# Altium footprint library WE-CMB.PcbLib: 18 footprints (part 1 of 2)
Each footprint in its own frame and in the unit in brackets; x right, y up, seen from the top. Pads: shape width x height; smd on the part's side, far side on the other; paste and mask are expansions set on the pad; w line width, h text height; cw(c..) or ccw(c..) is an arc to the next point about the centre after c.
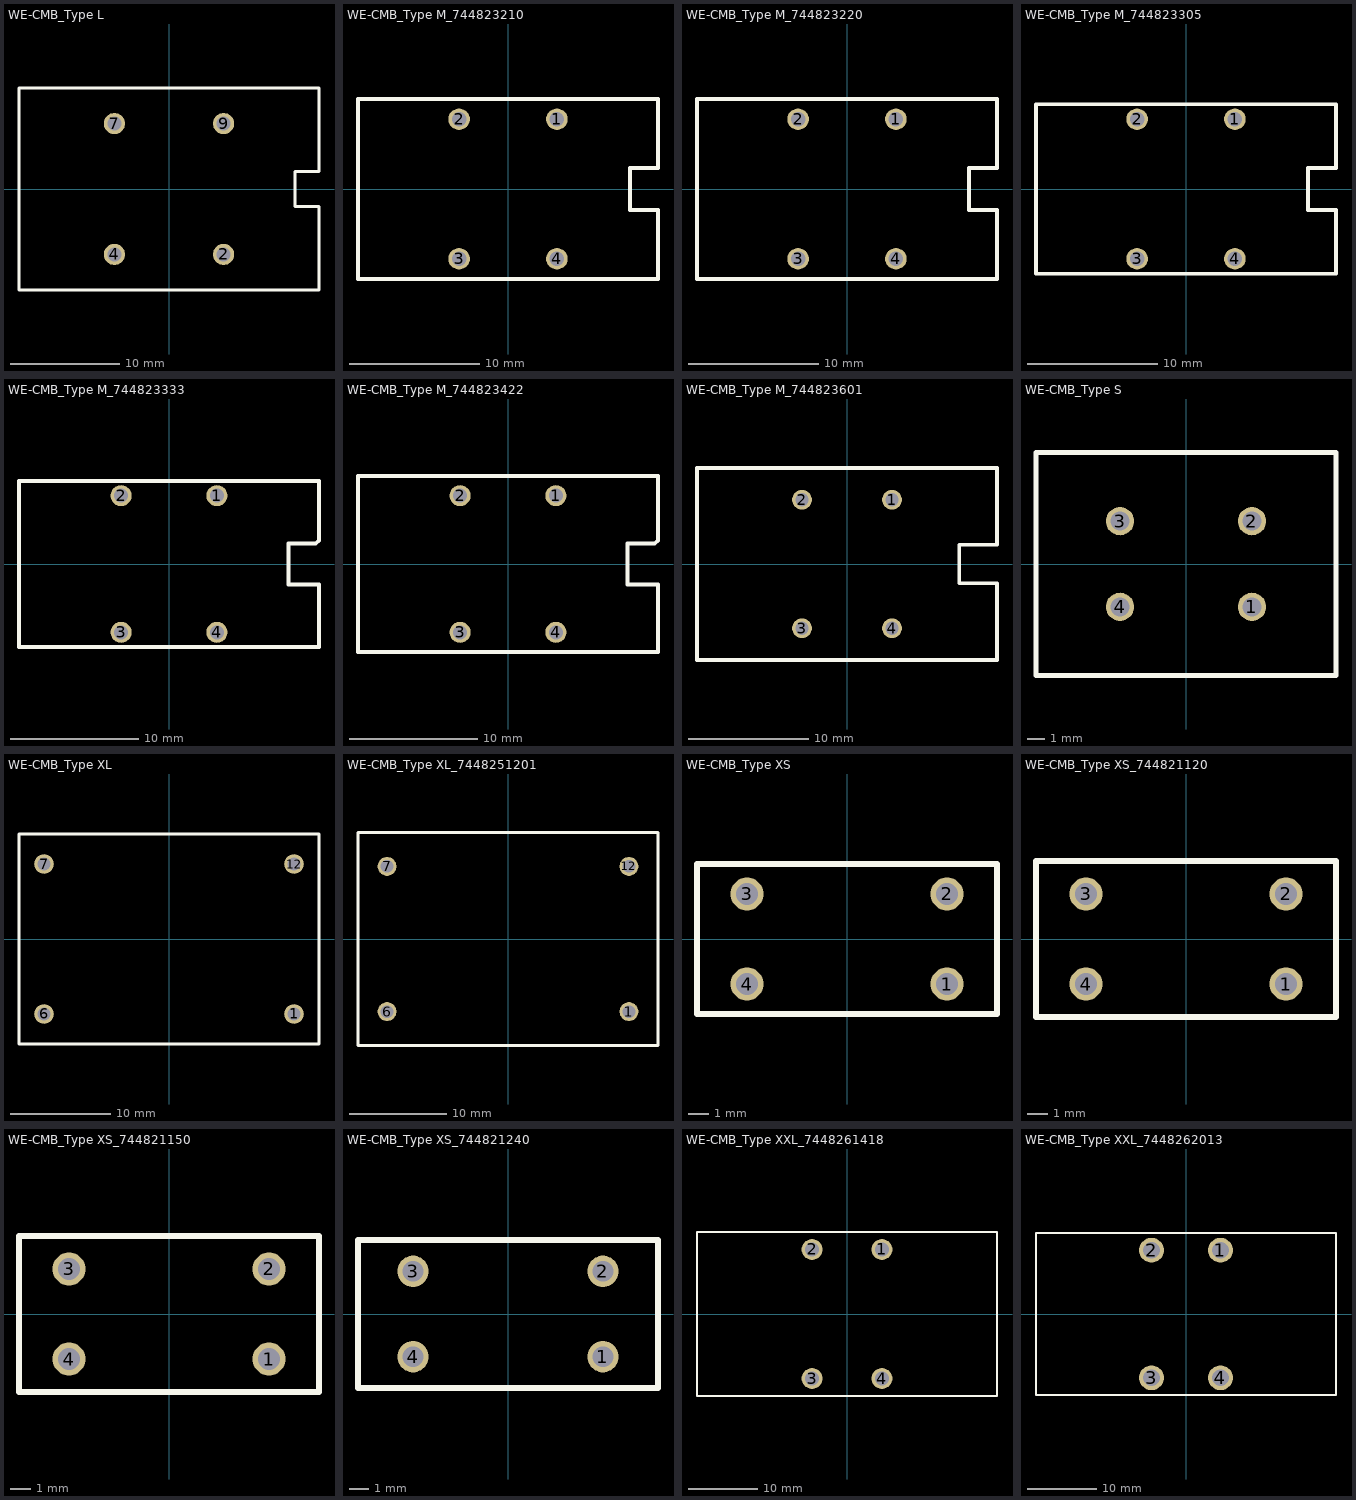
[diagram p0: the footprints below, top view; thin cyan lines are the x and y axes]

## WE-CMB_Type L [mm] "Common Mode Power Line Choke"
height 33
pads (4):
  round 1.95 hole 1.3: 2(5,-6) 4(-5,-6) 7(-5,6) 9(5,6)
Top Overlay:
  lines w0.3: -13.75,-9.25 -13.75,9.25 13.75,9.25 13.75,1.6 11.55,1.6 11.55,-1.6 13.75,-1.6 13.75,-9.25 -13.75,-9.25
3D body: height 33.1, standoff -4.9, extent -13.75,-9.25 13.75,9.25

## WE-CMB_Type M_744823210 [mm] "Common Mode Power Line Choke"
height 25.5
pads (4):
  round 1.65 hole 1.1: 1(3.75,5.35) 2(-3.75,5.35) 3(-3.75,-5.35) 4(3.75,-5.35)
Top Overlay:
  lines w0.3: 11.5,1.6 11.5,6.9 -11.5,6.9 -11.5,-6.9 11.5,-6.9 11.5,-1.6 9.35,-1.6 9.35,1.6 11.5,1.6 ; 11.5,1.6 11.5,1.6
3D body: height 23.3, standoff -4.8, extent -9.55,-6.5 9.55,6.5

## WE-CMB_Type M_744823220 [mm] "Common Mode Power Line Choke"
height 25.5
pads (4):
  round 1.65 hole 1.1: 1(3.75,5.35) 2(-3.75,5.35) 3(-3.75,-5.35) 4(3.75,-5.35)
Top Overlay:
  lines w0.3: 11.5,1.6 11.5,6.9 -11.5,6.9 -11.5,-6.9 11.5,-6.9 11.5,-1.6 9.35,-1.6 9.35,1.6 11.5,1.6 ; 11.5,1.6 11.5,1.6
3D body: height 23.3, standoff -4.8, extent -9.55,-6.5 9.55,6.5

## WE-CMB_Type M_744823305 [mm] "Common Mode Power Line Choke"
height 25.5
pads (4):
  round 1.65 hole 1.1: 1(3.75,5.35) 2(-3.75,5.35) 3(-3.75,-5.35) 4(3.75,-5.35)
Top Overlay:
  lines w0.3: 11.5,1.6 11.5,1.6 ; 11.5,1.6 9.35,1.6 9.35,-1.6 11.5,-1.6 11.5,-6.5 -11.5,-6.5 -11.5,6.5 11.5,6.5 11.5,1.6
3D body: height 23.3, standoff -4.8, extent -9.55,-6.5 9.55,6.5

## WE-CMB_Type M_744823333 [mm] "Common Mode Power Line Choke"
height 25.5
pads (4):
  round 1.65 hole 1.1: 1(3.75,5.35) 2(-3.75,5.35) 3(-3.75,-5.35) 4(3.75,-5.35)
Top Overlay:
  lines w0.3: -11.75,-6.5 -11.75,6.5 11.75,6.5 11.75,1.85 11.5,1.6 9.35,1.6 9.35,-1.6 11.75,-1.6 11.75,-6.5 -11.75,-6.5
3D body: height 23.3, standoff -4.8, extent -9.55,-6.5 9.55,6.5

## WE-CMB_Type M_744823422 [mm] "Common Mode Power Line Choke"
height 25.5
pads (4):
  round 1.65 hole 1.1: 1(3.75,5.35) 2(-3.75,5.35) 3(-3.75,-5.35) 4(3.75,-5.35)
Top Overlay:
  lines w0.3: -11.75,-6.9 -11.75,6.9 11.75,6.9 11.75,1.85 11.5,1.6 9.35,1.6 9.35,-1.6 11.75,-1.6 11.75,-6.9 -11.75,-6.9
3D body: height 23.3, standoff -4.8, extent -9.55,-6.5 9.55,6.5

## WE-CMB_Type M_744823601 [mm] "Common Mode Power Line Choke"
height 26.5
pads (4):
  round 1.65 hole 1.1: 1(3.75,5.35) 2(-3.75,5.35) 3(-3.75,-5.35) 4(3.75,-5.35)
Top Overlay:
  lines w0.3: -12.5,-8 12.5,-8 12.5,-1.6 9.35,-1.6 9.35,1.6 12.5,1.6 12.5,8 -12.5,8 -12.5,-8
3D body: height 23.3, standoff -4.8, extent -9.55,-6.5 9.55,6.5

## WE-CMB_Type S [mm] "Common Mode Power Line Choke"
height 22
pads (4):
  round 1.65 hole 1.1: 1(3.85,-2.5) 2(3.85,2.5) 3(-3.85,2.5) 4(-3.85,-2.5)
Top Overlay:
  lines w0.3: -8.75,-6.5 -8.75,6.5 8.75,6.5 8.75,-6.5 -8.75,-6.5
3D body: height 20.2, standoff -2.8, extent -7.768,-6.5 7.77,6.5

## WE-CMB_Type XL [mm] "Common Mode Power Line Choke"
height 35
pads (4):
  round 1.95 hole 1.3: 1(12.5,-7.5) 6(-12.5,-7.5) 7(-12.5,7.5) 12(12.5,7.5)
Top Overlay:
  lines w0.3: -15,-10.5 -15,10.5 15,10.5 15,-10.5 -15,-10.5
3D body: height 35.25, standoff -4.88, extent -15.5,-11 15.5,11

## WE-CMB_Type XL_7448251201 [mm] "Common Mode Power Line Choke"
height 35
pads (4):
  round 1.95 hole 1.3: 1(12.5,-7.5) 6(-12.5,-7.5) 7(-12.5,7.5) 12(12.5,7.5)
Top Overlay:
  lines w0.3: -15.5,-11 -15.5,11 15.5,11 15.5,-11 -15.5,-11
3D body: height 35.25, standoff -4.88, extent -15.5,-11 15.5,11

## WE-CMB_Type XS [mm] "Common Mode Power Line Choke"
height 18
pads (4):
  round 1.65 hole 1.1: 1(5,-2.25) 2(5,2.25) 3(-5,2.25) 4(-5,-2.25)
Top Overlay:
  lines w0.3: -7.5,-3.75 7.5,-3.75 7.5,3.75 -7.5,3.75 -7.5,-3.75
3D body: height 16.34, standoff -3.48, extent -6.897,-3.75 6.897,3.75

## WE-CMB_Type XS_744821120 [mm] "Common Mode Power Line Choke"
height 17.5
pads (4):
  round 1.65 hole 1.1: 1(5,-2.25) 2(5,2.25) 3(-5,2.25) 4(-5,-2.25)
Top Overlay:
  lines w0.3: -7.5,-3.9 -7.5,3.9 7.5,3.9 7.5,-3.9 -7.5,-3.9
3D body: height 16.34, standoff -3.48, extent -6.897,-3.75 6.897,3.75

## WE-CMB_Type XS_744821150 [mm] "Common Mode Power Line Choke"
height 18
pads (4):
  round 1.65 hole 1.1: 1(5,-2.25) 2(5,2.25) 3(-5,2.25) 4(-5,-2.25)
Top Overlay:
  lines w0.3: -7.5,-3.9 7.5,-3.9 7.5,3.9 -7.5,3.9 -7.5,-3.9
3D body: height 16.34, standoff -3.48, extent -6.897,-3.75 6.897,3.75

## WE-CMB_Type XS_744821240 [mm] "Common Mode Power Line Choke"
height 18
pads (4):
  round 1.65 hole 1.1: 1(5,-2.25) 2(5,2.25) 3(-5,2.25) 4(-5,-2.25)
Top Overlay:
  lines w0.3: -7.9,-3.9 7.9,-3.9 7.9,3.9 -7.9,3.9 -7.9,-3.9
3D body: height 16.34, standoff -3.48, extent -6.897,-3.75 6.897,3.75

## WE-CMB_Type XXL_7448261418 [mm] "Common Mode Power Line Choke"
height 43
pads (4):
  round 3 hole 2: 1(5,9.25) 2(-5,9.25) 3(-5,-9.25) 4(5,-9.25)
Top Overlay:
  lines w0.3: -21.5,-11.75 -21.5,11.75 21.5,11.75 21.5,-11.75 -21.5,-11.75
3D body: height 39.64, standoff -4.95, extent -19.562,-11.5 19.561,11.5

## WE-CMB_Type XXL_7448262013 [mm] "Common Mode Power Line Choke"
height 43
pads (4):
  round 3.6 hole 2.4: 1(5,9.25) 2(-5,9.25) 3(-5,-9.25) 4(5,-9.25)
Top Overlay:
  lines w0.3: -21.75,-11.75 21.75,-11.75 21.75,11.75 -21.75,11.75 -21.75,-11.75
3D body: height 39.85, standoff -4.75, extent -20.001,-11.5 20,11.5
